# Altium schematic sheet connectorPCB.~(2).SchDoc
size A; SheetNumber: 2; SheetTotal: 2
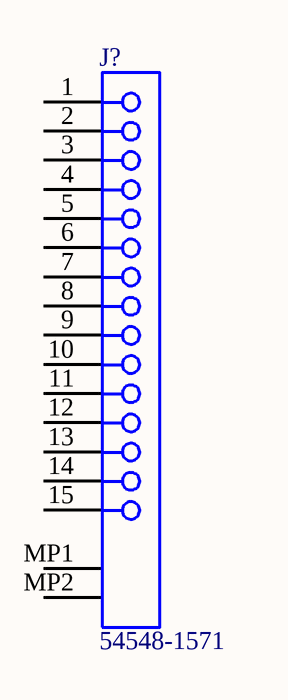
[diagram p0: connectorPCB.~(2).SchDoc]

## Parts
J?  54548-1571  [MOLX-54548-1571]

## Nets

Not connected (* = marked no-connect by the designer): J? 1 2 3 4 5 6 7 8 9 10 11 12 13 14 15 MP1 MP2

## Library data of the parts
J? = CMP-1241-00549-1: 0.5 mm Pitch Easy-On(TM) Type FPC Connector, 1.2 mm Mated Height, Right Angle, ZIF, SMT, Bottom Contact, 15 Circuits, -20 to 85 degC, ELV and RoHS Compliant, Tape and Reel; Manufacturer: Molex; Stackable: No; Current (Max per Contact): 0.5A; Mated Height: 1.20mm; Entry Angle: 90degrees Angle; Polarized to PCB: Yes; Material - Plating Mating: Gold; Durability (mating cycles max): 20; Circuits (Loaded): 15; Material - Plating Termination: Tin; Material - Metal: Phosphor Bronze; Pitch - Mating Interface: 0.50mm; Voltage (Max): 50V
